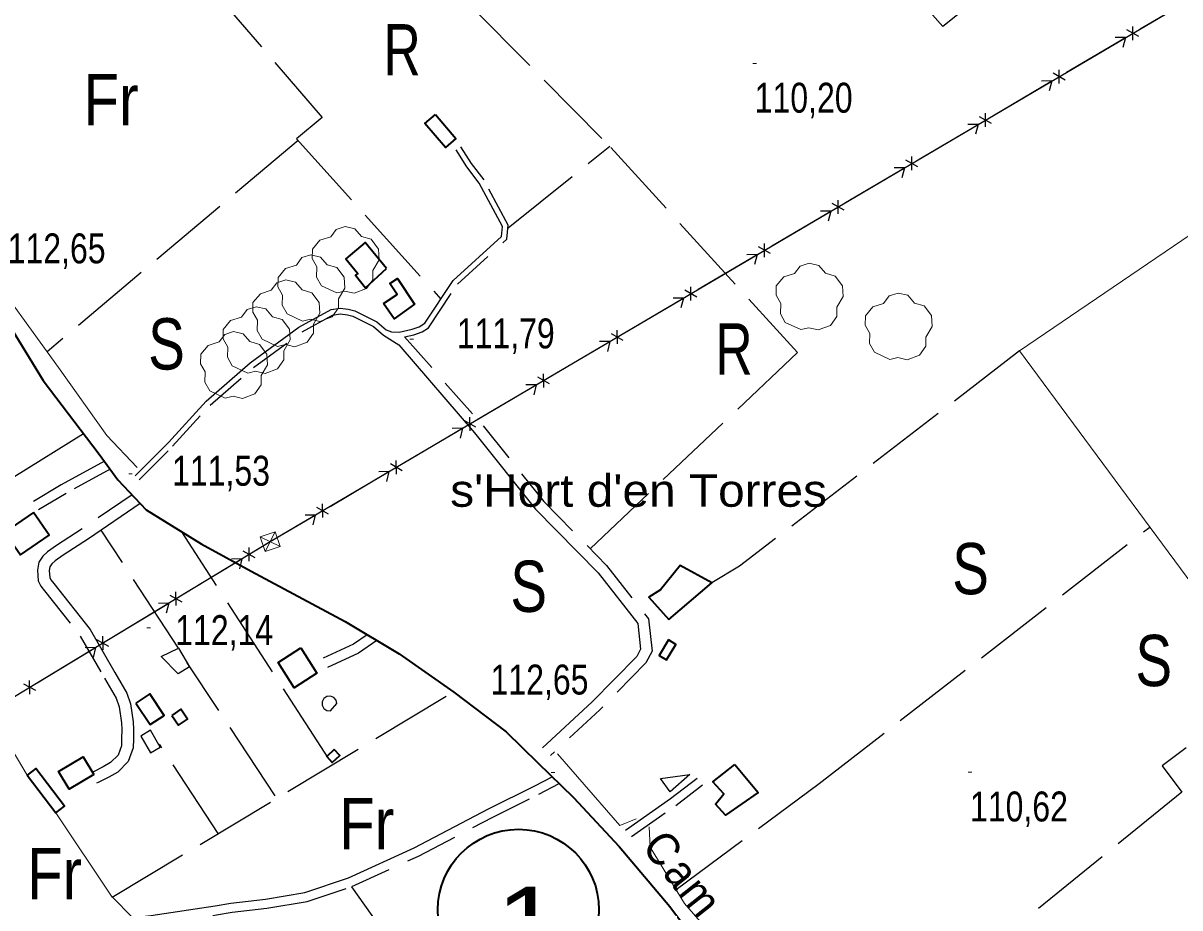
# Model space of a CAD drawing. Extents: x 483840 to 488445, y 4386047 to 4389027.
# Drawn here: x 486022 to 486360.3, y 4387708.7 to 4387967.4 of the extents above; entities that cross this region are included whole.
import ezdxf
from ezdxf.enums import TextEntityAlignment as Align

# ---------------------------------------------------------------- set-up
doc = ezdxf.new("R2010")
doc.units = 0
doc.header["$LTSCALE"] = 4
doc.linetypes.add('LONG_DASHED', pattern=[7.5, 6, -1.5])
doc.linetypes.add('MEDIUM_DASHED', pattern=[4.5, 3, -1.5])
for name, color, linetype, lineweight in [('21', 7, 'Continuous', 25), ('25', 7, 'LONG_DASHED', 25), ('29', 7, 'Continuous', 13), ('38', 7, 'Continuous', 25), ('43', 7, 'Continuous', 25), ('47', 7, 'Continuous', 35), ('51', 7, 'Continuous', 13), ('6', 7, 'Continuous', 35), ('7', 7, 'Continuous', 13)]:
    doc.layers.add(name, color=color, linetype=linetype, lineweight=lineweight)
doc.layers.add('31', color=7, linetype='Continuous')
doc.layers.add('5', color=7, linetype='Continuous')

msp = doc.modelspace()

# ---------------------------------------------------------------- linework, layer by layer
at = {"layer": '21'}
for points in [[(486067.44, 4387784.6), (486070.74, 4387779.23), (486067.41, 4387777.18), (486062.45, 4387782.2)], [(486113.81, 4387768.47), (486113.56, 4387769.48), (486112.87, 4387770.26), (486111.9, 4387770.62), (486110.87, 4387770.5), (486110.02, 4387769.91), (486109.53, 4387768.99), (486109.53, 4387767.95), (486110.02, 4387767.03), (486110.87, 4387766.44), (486111.9, 4387766.31)], [(486056.42, 4387758.95), (486059.25, 4387754.05), (486062.15, 4387755.72), (486059.32, 4387760.62)], [(486216.99, 4387747.72), (486211.28, 4387742.62), (486208.41, 4387746.49)]]:
    msp.add_lwpolyline(points, close=True, dxfattribs=at)
at = {"layer": '25'}
for p, q in [((486102.47, 4387933.11), (486029.07, 4387871.28)), ((486163.83, 4387907.56), (486193.58, 4387931.4)), ((486313.37, 4387871.53), (486231.56, 4387808.61)), ((486039.73, 4387847.35), (485983.43, 4387812.19)), ((486067.44, 4387784.6), (486044.9, 4387819.17)), ((486111.24, 4387752.57), (486068.41, 4387818.63)), ((486231.56, 4387808.61), (486223.42, 4387803.76)), ((486095.79, 4387741.43), (486070.04, 4387780.39)), ((486048.09, 4387711.8), (486147.81, 4387771.87)), ((486079.06, 4387730.46), (486061.94, 4387756.54)), ((486118.08, 4387714.88), (486158.23, 4387658.26)), ((486047.94, 4387712.03), (486054.15, 4387705.84))]:
    msp.add_line(p, q, dxfattribs=at)
for points in [[(486098.57, 4388032.63), (486144.95, 4387971.17), (486153.27, 4387972.01), (486193.92, 4387931.04), (486248.48, 4387871.04), (486187.86, 4387813.71)], [(486349.61, 4388013.75), (486291.01, 4387966.38), (486277.36, 4387981.77)], [(486056.48, 4388001.3), (486109.52, 4387939.83), (486102.03, 4387933.59), (486144.18, 4387886.7)], [(486212.97, 4387714.12), (486254.84, 4387745.08), (486351.49, 4387820.05)], [(486386.11, 4387773.51), (486355.09, 4387750.24), (486360.91, 4387742.58), (486313.23, 4387703.87), (486259.09, 4387660.2)]]:
    msp.add_lwpolyline(points, dxfattribs=at)
at = {"layer": '29'}
for points in [[(486113.81, 4387888.49), (486109.27, 4387890.61), (486107.86, 4387893.15), (486107.96, 4387896.13), (486106.59, 4387898.54), (486106.63, 4387901.29), (486108.79, 4387903.89), (486111.98, 4387904.89), (486113.63, 4387907.08), (486116.2, 4387907.91), (486119.06, 4387907.26), (486121.01, 4387904.99), (486123.82, 4387904.17), (486125.95, 4387901.32), (486126.19, 4387898.19), (486124.31, 4387895.04), (486124.31, 4387892.36), (486122.49, 4387889.75), (486118.87, 4387888.41), (486116.1, 4387889.04)], [(486103.77, 4387880.23), (486099.23, 4387882.35), (486097.82, 4387884.89), (486097.92, 4387887.87), (486096.55, 4387890.28), (486096.59, 4387893.03), (486098.75, 4387895.63), (486101.94, 4387896.63), (486103.59, 4387898.82), (486106.16, 4387899.65), (486109.02, 4387899), (486110.97, 4387896.73), (486113.78, 4387895.91), (486115.91, 4387893.06), (486116.15, 4387889.93), (486114.27, 4387886.78), (486114.27, 4387884.1), (486112.45, 4387881.49), (486108.83, 4387880.15), (486106.06, 4387880.78)], [(486249.46, 4387877.76), (486244.92, 4387879.88), (486243.51, 4387882.42), (486243.61, 4387885.4), (486242.24, 4387887.81), (486242.28, 4387890.56), (486244.44, 4387893.16), (486247.63, 4387894.16), (486249.28, 4387896.35), (486251.85, 4387897.18), (486254.71, 4387896.53), (486256.66, 4387894.26), (486259.47, 4387893.44), (486261.6, 4387890.59), (486261.84, 4387887.46), (486259.96, 4387884.31), (486259.96, 4387881.63), (486258.14, 4387879.02), (486254.52, 4387877.68), (486251.75, 4387878.31)], [(486096.44, 4387872.86), (486091.9, 4387874.98), (486090.49, 4387877.52), (486090.59, 4387880.5), (486089.22, 4387882.91), (486089.26, 4387885.66), (486091.42, 4387888.26), (486094.61, 4387889.26), (486096.26, 4387891.45), (486098.83, 4387892.28), (486101.69, 4387891.63), (486103.64, 4387889.36), (486106.45, 4387888.54), (486108.58, 4387885.69), (486108.82, 4387882.56), (486106.94, 4387879.41), (486106.94, 4387876.73), (486105.12, 4387874.12), (486101.5, 4387872.78), (486098.73, 4387873.41)], [(486275.5, 4387869.03), (486270.96, 4387871.15), (486269.55, 4387873.69), (486269.65, 4387876.67), (486268.28, 4387879.08), (486268.32, 4387881.83), (486270.48, 4387884.43), (486273.67, 4387885.43), (486275.32, 4387887.62), (486277.89, 4387888.45), (486280.75, 4387887.8), (486282.7, 4387885.53), (486285.51, 4387884.71), (486287.64, 4387881.86), (486287.88, 4387878.73), (486286, 4387875.58), (486286, 4387872.9), (486284.18, 4387870.29), (486280.56, 4387868.95), (486277.79, 4387869.58)], [(486087.75, 4387865.05), (486083.21, 4387867.17), (486081.8, 4387869.71), (486081.9, 4387872.69), (486080.53, 4387875.1), (486080.57, 4387877.85), (486082.73, 4387880.45), (486085.92, 4387881.45), (486087.57, 4387883.64), (486090.14, 4387884.47), (486093, 4387883.82), (486094.95, 4387881.55), (486097.76, 4387880.73), (486099.89, 4387877.88), (486100.13, 4387874.75), (486098.25, 4387871.6), (486098.25, 4387868.92), (486096.43, 4387866.31), (486092.81, 4387864.97), (486090.04, 4387865.6)], [(486081.16, 4387857.76), (486076.62, 4387859.88), (486075.21, 4387862.42), (486075.31, 4387865.4), (486073.94, 4387867.81), (486073.98, 4387870.56), (486076.14, 4387873.16), (486079.33, 4387874.16), (486080.98, 4387876.35), (486083.55, 4387877.18), (486086.41, 4387876.53), (486088.36, 4387874.26), (486091.17, 4387873.44), (486093.3, 4387870.59), (486093.54, 4387867.46), (486091.66, 4387864.31), (486091.66, 4387861.63), (486089.84, 4387859.02), (486086.22, 4387857.68), (486083.45, 4387858.31)]]:
    msp.add_lwpolyline(points, close=True, dxfattribs=at)
at = {"layer": '38', "linetype": 'MEDIUM_DASHED'}
for points in [[(486133.57, 4387875.64), (486136.33, 4387876.24), (486138.73, 4387877.08), (486140.61, 4387878.28), (486149.03, 4387891.04), (486163.49, 4387904.17), (486163.9, 4387908.29), (486156.83, 4387921.52), (486153.11, 4387926.35), (486150.08, 4387931.23)], [(486055.96, 4387833.82), (486065.77, 4387843.66), (486076.74, 4387855.71), (486089.43, 4387866.73), (486103.6, 4387877.08), (486112.52, 4387882.03), (486114.73, 4387882.38), (486116.94, 4387882.1), (486118.5, 4387881.74), (486124.52, 4387878.64), (486127.43, 4387876.14), (486131.95, 4387873.31)], [(486133.57, 4387875.64), (486156.55, 4387849.67), (486174.31, 4387827.48), (486192.66, 4387808.82), (486204.96, 4387793.17), (486205.94, 4387783.79)], [(486047.49, 4387836.98), (486034.61, 4387829.9), (486026.54, 4387825.08)], [(486053.9, 4387829.46), (486039.3, 4387819.51), (486031.79, 4387814.66), (486029.18, 4387812.84), (486027.81, 4387811.51), (486026.6, 4387809.77), (486026.23, 4387807.46), (486026.48, 4387804.34), (486027.22, 4387802.81), (486028.33, 4387801.4), (486038.77, 4387788.17), (486045.87, 4387775.83), (486049.26, 4387770.04), (486050.12, 4387767.53), (486050.82, 4387762.77), (486050.87, 4387760.86), (486050.83, 4387758.21), (486050.79, 4387756.13), (486049.79, 4387753.39), (486047.64, 4387751.19), (486045.48, 4387749.99), (486042.58, 4387748.52), (486042.35, 4387748.42)], [(486125.46, 4387786.88), (486120.15, 4387783.16), (486111.02, 4387779)], [(486205.94, 4387783.79), (486204.17, 4387780.33), (486190.65, 4387766.59), (486176.28, 4387753.25)], [(485958.52, 4387746.61), (485975.62, 4387715.98), (485983.06, 4387705.11), (485984.97, 4387701.93), (485989.62, 4387699.04), (485993.18, 4387698.99), (486006.76, 4387700.54), (486042.06, 4387701.68), (486059.76, 4387703.77), (486078.61, 4387706.66), (486083.17, 4387707.41), (486093.32, 4387708.61), (486105.11, 4387710.59), (486118.19, 4387714.92), (486137.61, 4387723.87), (486159.41, 4387735.2), (486172.87, 4387741.98), (486178.82, 4387745.07)], [(486199.96, 4387729.6), (486212.87, 4387738.62), (486220.71, 4387744.68)]]:
    msp.add_lwpolyline(points, dxfattribs=at)
at = {"layer": '38'}
for points in [[(486054.79, 4387834.99), (486064.57, 4387844.81), (486075.58, 4387856.9), (486088.4, 4387868.03), (486102.71, 4387878.48), (486112.08, 4387883.67), (486114.73, 4387884.05), (486117.11, 4387883.75), (486119.07, 4387883.31), (486125.45, 4387880.02), (486128.16, 4387877.69), (486129.73, 4387877.15), (486131.97, 4387877.03), (486135.8, 4387877.92), (486137.83, 4387878.54), (486139.54, 4387879.66), (486147.76, 4387892.12), (486161.91, 4387904.97), (486162.21, 4387907.96), (486155.44, 4387920.62), (486151.75, 4387925.41), (486148.67, 4387930.36)], [(486131.95, 4387873.31), (486154.06, 4387847.57), (486171.87, 4387825.31), (486190.21, 4387806.66), (486201.82, 4387791.89), (486202.6, 4387784.36)], [(486045.83, 4387839.33), (486033.19, 4387832.39), (486025.07, 4387827.54)], [(486056.28, 4387826.91), (486041.2, 4387816.64), (486033.71, 4387811.81), (486031.38, 4387810.18), (486030.45, 4387809.27), (486029.88, 4387808.45), (486029.7, 4387807.33), (486029.86, 4387805.26), (486030.16, 4387804.64), (486031.04, 4387803.52), (486041.62, 4387790.1), (486048.84, 4387777.56), (486052.41, 4387771.49), (486053.48, 4387768.35), (486054.26, 4387763.06), (486054.31, 4387760.87), (486054.27, 4387758.15), (486054.23, 4387755.49), (486052.76, 4387751.52), (486049.75, 4387748.43), (486047.09, 4387746.95), (486044.02, 4387745.39), (486043.45, 4387745.15)], [(486122.63, 4387788.57), (486118.65, 4387785.79), (486109.77, 4387781.74)], [(486202.6, 4387784.36), (486201.52, 4387782.24), (486188.4, 4387768.91), (486173.95, 4387755.5)], [(485960.89, 4387747.94), (485977.93, 4387717.41), (485985.34, 4387706.58), (485986.96, 4387703.89), (485990.41, 4387701.74), (485993.05, 4387701.71), (486006.57, 4387703.25), (486041.85, 4387704.39), (486059.4, 4387706.46), (486078.18, 4387709.34), (486082.78, 4387710.1), (486092.93, 4387711.3), (486104.45, 4387713.23), (486117.2, 4387717.45), (486136.41, 4387726.31), (486158.17, 4387737.62), (486171.63, 4387744.4), (486176.77, 4387747.06)], [(486198.14, 4387731.41), (486211.36, 4387740.66), (486219.16, 4387746.68)]]:
    msp.add_lwpolyline(points, dxfattribs=at)
at = {"layer": '43'}
for p, q in [((486348.71, 4387965.7), (486365.94, 4387975.86)), ((486348.3, 4387963.44), (486344.82, 4387965.41)), ((486346.57, 4387962.43), (486346.54, 4387966.42)), ((486327.17, 4387953.01), (486344.4, 4387963.16)), ((486344.4, 4387963.16), (486341.4, 4387963.14)), ((486344.4, 4387963.16), (486343.65, 4387960.26)), ((486326.76, 4387950.75), (486323.28, 4387952.72)), ((486325.03, 4387949.74), (486325, 4387953.73)), ((486305.63, 4387940.32), (486322.86, 4387950.47)), ((486322.86, 4387950.47), (486319.86, 4387950.45)), ((486322.86, 4387950.47), (486322.11, 4387947.57)), ((486305.22, 4387938.06), (486301.74, 4387940.02)), ((486303.5, 4387937.04), (486303.46, 4387941.04)), ((486284.09, 4387927.63), (486301.32, 4387937.78)), ((486301.32, 4387937.78), (486298.32, 4387937.75)), ((486301.32, 4387937.78), (486300.57, 4387934.88)), ((486281.96, 4387924.35), (486281.92, 4387928.35)), ((486262.55, 4387914.94), (486279.78, 4387925.09)), ((486279.78, 4387925.09), (486276.78, 4387925.06)), ((486279.78, 4387925.09), (486279.03, 4387922.19)), ((486283.68, 4387925.37), (486280.2, 4387927.33)), ((486262.14, 4387912.67), (486258.66, 4387914.64)), ((486260.42, 4387911.66), (486260.38, 4387915.66)), ((486241.01, 4387902.24), (486258.24, 4387912.4)), ((486258.24, 4387912.4), (486255.24, 4387912.37)), ((486258.24, 4387912.4), (486257.49, 4387909.49)), ((486240.6, 4387899.98), (486237.12, 4387901.95)), ((486238.88, 4387898.97), (486238.85, 4387902.96)), ((486219.47, 4387889.55), (486236.7, 4387899.71)), ((486236.7, 4387899.71), (486233.7, 4387899.68)), ((486236.7, 4387899.71), (486235.95, 4387896.8)), ((486219.06, 4387887.29), (486215.58, 4387889.26)), ((486217.34, 4387886.28), (486217.31, 4387890.27)), ((486197.93, 4387876.86), (486215.17, 4387887.01)), ((486215.17, 4387887.01), (486212.16, 4387886.99)), ((486215.17, 4387887.01), (486214.41, 4387884.11)), ((486195.8, 4387873.58), (486195.77, 4387877.58)), ((486176.4, 4387864.17), (486193.63, 4387874.32)), ((486193.63, 4387874.32), (486190.62, 4387874.29)), ((486193.63, 4387874.32), (486192.88, 4387871.42)), ((486197.53, 4387874.6), (486194.05, 4387876.56)), ((486175.99, 4387861.91), (486172.51, 4387863.87)), ((486174.26, 4387860.89), (486174.23, 4387864.89)), ((486154.86, 4387851.48), (486172.09, 4387861.63)), ((486172.09, 4387861.63), (486169.09, 4387861.6)), ((486172.09, 4387861.63), (486171.34, 4387858.73)), ((486154.45, 4387849.22), (486150.97, 4387851.18)), ((486152.72, 4387848.2), (486152.69, 4387852.2)), ((486133.32, 4387838.78), (486150.55, 4387848.94)), ((486150.55, 4387848.94), (486147.55, 4387848.91)), ((486150.55, 4387848.94), (486149.8, 4387846.03)), ((486132.91, 4387836.52), (486129.43, 4387838.49)), ((486131.19, 4387835.51), (486131.15, 4387839.5)), ((486111.78, 4387826.09), (486129.01, 4387836.25)), ((486129.01, 4387836.25), (486126.01, 4387836.22)), ((486129.01, 4387836.25), (486128.26, 4387833.34)), ((486109.65, 4387822.82), (486109.61, 4387826.81)), ((486107.47, 4387823.55), (486104.47, 4387823.53)), ((486107.47, 4387823.55), (486106.72, 4387820.65)), ((486111.37, 4387823.83), (486107.89, 4387825.8)), ((486089.89, 4387811.08), (486086.39, 4387813.01)), ((486088.18, 4387810.05), (486088.1, 4387814.04)), ((486068.89, 4387800.4), (486085.99, 4387810.76)), ((486085.99, 4387810.76), (486082.99, 4387810.69)), ((486085.99, 4387810.76), (486085.28, 4387807.85)), ((486068.51, 4387798.13), (486065, 4387800.05)), ((486066.8, 4387797.09), (486066.71, 4387801.09)), ((486047.51, 4387787.44), (486064.61, 4387797.8)), ((486064.61, 4387797.8), (486061.61, 4387797.74)), ((486064.61, 4387797.8), (486063.9, 4387794.89)), ((486047.13, 4387785.17), (486043.62, 4387787.1)), ((486045.42, 4387784.14), (486045.33, 4387788.13)), ((486026.13, 4387774.49), (486043.23, 4387784.85)), ((486043.23, 4387784.85), (486040.23, 4387784.78)), ((486043.23, 4387784.85), (486042.52, 4387781.94)), ((486025.74, 4387772.22), (486022.24, 4387774.14)), ((486024.03, 4387771.18), (486023.95, 4387775.18))]:
    msp.add_line(p, q, dxfattribs=at)
at = {"layer": '43', "lineweight": 13}
for p, q in [((486091.4, 4387817.2), (486097.18, 4387814.35)), ((486095.74, 4387818.65), (486092.84, 4387812.9))]:
    msp.add_line(p, q, dxfattribs=at)
at = {"layer": '43'}
for points in [[(485790.93, 4387631.98), (486094.33, 4387815.81), (486392.84, 4387991.71)], [(486090.27, 4387813.35), (486094.33, 4387815.81), (486107.47, 4387823.55)]]:
    msp.add_lwpolyline(points, dxfattribs=at)
at = {"layer": '43', "lineweight": 13}
msp.add_lwpolyline([(486091.4, 4387817.2), (486095.74, 4387818.65), (486097.18, 4387814.35), (486092.84, 4387812.9)], close=True, dxfattribs=at)
at = {"layer": '47'}
for points in [[(486142.6, 4387940.63), (486148.61, 4387933.67), (486145.52, 4387931.01), (486139.5, 4387937.99)], [(486128.34, 4387895.68), (486122.1, 4387903.24), (486116.36, 4387898.51), (486119.9, 4387894.2), (486119.24, 4387893.67), (486122.17, 4387890.01)], [(486127.46, 4387885.4), (486131.43, 4387888.03), (486129.28, 4387891.26), (486131.47, 4387892.72), (486136.45, 4387885.23), (486130.54, 4387880.9)], [(486025.09, 4387824.31), (486016.73, 4387818.55), (486021.31, 4387811.9), (486029.67, 4387817.66)], [(486210.88, 4387792.98), (486223.42, 4387803.76), (486214.18, 4387808.76), (486208.45, 4387801.72), (486204.97, 4387799.52)], [(486210.72, 4387787.05), (486208, 4387782.53), (486210.19, 4387781.21), (486212.91, 4387785.73)], [(486103.23, 4387784.69), (486107.96, 4387777.35), (486101.34, 4387773.09), (486096.61, 4387780.43)], [(486054.98, 4387768.58), (486059.16, 4387762.28), (486063.26, 4387765), (486059.08, 4387771.3)], [(486065.51, 4387764.97), (486067.52, 4387762.09), (486070.15, 4387763.93), (486068.14, 4387766.81)], [(486042.75, 4387747.74), (486035.52, 4387743.39), (486032.41, 4387748.56), (486039.64, 4387752.91)], [(486113.01, 4387754.99), (486110.83, 4387753.01), (486112.43, 4387751.24), (486114.61, 4387753.22)], [(486023.24, 4387747.49), (486031.58, 4387736.47), (486034.14, 4387738.41), (486025.8, 4387749.43)], [(486230.16, 4387750.61), (486237.02, 4387742.41), (486227.47, 4387735.79), (486224.51, 4387739.06), (486226.96, 4387742.02), (486223.71, 4387745.6)]]:
    msp.add_lwpolyline(points, close=True, dxfattribs=at)
at = {"layer": '51'}
for p, q in [((486005.51, 4387777.21), (486023.25, 4387747.48)), ((486031.58, 4387736.47), (486048.09, 4387711.8))]:
    msp.add_line(p, q, dxfattribs=at)
for points in [[(486055.38, 4387837.5), (486046.51, 4387846.86), (486032.37, 4387866.72), (486009.59, 4387898.11), (485979.75, 4387938.64), (485951.94, 4387972.13), (485930.82, 4387996.62), (485910.45, 4388018.27)], [(486408.38, 4387936.12), (486313.37, 4387871.53), (486379.6, 4387782.07)], [(486178.35, 4387753.75), (486196.51, 4387732.78), (486201.27, 4387734.74)], [(486205.06, 4387732.43), (486205.43, 4387726.5), (486215.47, 4387710), (486254.96, 4387664.64), (486262.72, 4387656.27), (486288.49, 4387627.24), (486311.98, 4387601.16)]]:
    msp.add_lwpolyline(points, dxfattribs=at)
at = {"layer": '6'}
for points in [[(485912.17, 4388011.78), (485935.61, 4387985.33), (485960.06, 4387956.84), (485983.16, 4387928.35), (486007.28, 4387896.47), (486027.88, 4387862.88), (486044.27, 4387841.38), (486049.75, 4387833.89), (486058.02, 4387825.05), (486074.09, 4387815.1), (486088.73, 4387807.17), (486116.23, 4387792.4)], [(486116.23, 4387792.4), (486132.03, 4387782.95), (486147.96, 4387771.75), (486163.27, 4387760.17), (486172.57, 4387751.14), (486183, 4387741), (486196.38, 4387726.7), (486211.2, 4387709.12), (486226.06, 4387689.1), (486244.26, 4387669.22), (486254.87, 4387655.62), (486266.52, 4387644.16), (486282.31, 4387626.78), (486304.74, 4387601.82), (486311.03, 4387591.7), (486319.95, 4387578.44), (486330.78, 4387563.95), (486337.26, 4387554.38), (486344.84, 4387544.52), (486353.11, 4387536.82), (486365.48, 4387527.49)]]:
    msp.add_lwpolyline(points, dxfattribs=at)
msp.add_circle((486166.88, 4387708.13), 23.55, dxfattribs=at)
at = {"layer": '7'}
for p, q in [((486235.47, 4387955.57), (486236.47, 4387955.57)), ((486135.15, 4387874.99), (486136.15, 4387874.99)), ((486052.96, 4387835.6), (486053.96, 4387835.6)), ((486058.25, 4387790.58), (486059.25, 4387790.58)), ((486176.5, 4387748.29), (486177.5, 4387748.29)), ((486298.43, 4387748.35), (486299.43, 4387748.35))]:
    msp.add_line(p, q, dxfattribs=at)

# ---------------------------------------------------------------- texts
at = {"layer": '31'}
for s, width, p in [('R', 0.75, (486132.88, 4387952.09)), ('Fr', 0.85, (486047.74, 4387937.49)), ('S', 0.8, (486063.97, 4387866.11)), ('R', 0.75, (486229.93, 4387864.62)), ('S', 0.8, (486299.09, 4387800.4)), ('S', 0.8, (486169.89, 4387795.24)), ('S', 0.8, (486352.66, 4387773.54)), ('Fr', 0.85, (486122.5, 4387725.86)), ('Fr', 0.85, (486031.24, 4387711.22))]:
    msp.add_text(s, height=15, dxfattribs=dict(at, width=width)).set_placement(p, align=Align.CENTER)
at = {"layer": '5', "width": 1.1}
msp.add_text("s'Hort d'en Torres", height=9.5, dxfattribs=at).set_placement((486257.1, 4387825.98), align=Align.RIGHT)
at = {"layer": '5', "width": 0.95}
for s, p in [('C', (486205.36, 4387723.09)), ('a', (486210.86, 4387716.14)), ('m', (486216.47, 4387709.07))]:
    msp.add_text(s, height=9.49, rotation=308.414, dxfattribs=at).set_placement(p, align=Align.CENTER)
at = {"layer": '6', "width": 1.25}
msp.add_text('1', height=20, dxfattribs=at).set_placement((486169.71, 4387694.88), align=Align.CENTER)
at = {"layer": '7', "width": 0.8}
for s, p in [('110,20', (486235.97, 4387941.2)), ('112,65', (486017.53, 4387897.15)), ('111,79', (486148.86, 4387872.28)), ('111,53', (486065.6, 4387832.13)), ('112,14', (486066.52, 4387785.54)), ('112,65', (486158.73, 4387771.09)), ('110,62', (486298.93, 4387733.98))]:
    msp.add_text(s, height=8.75, dxfattribs=at).set_placement(p)

doc.saveas('drawing.dxf')
